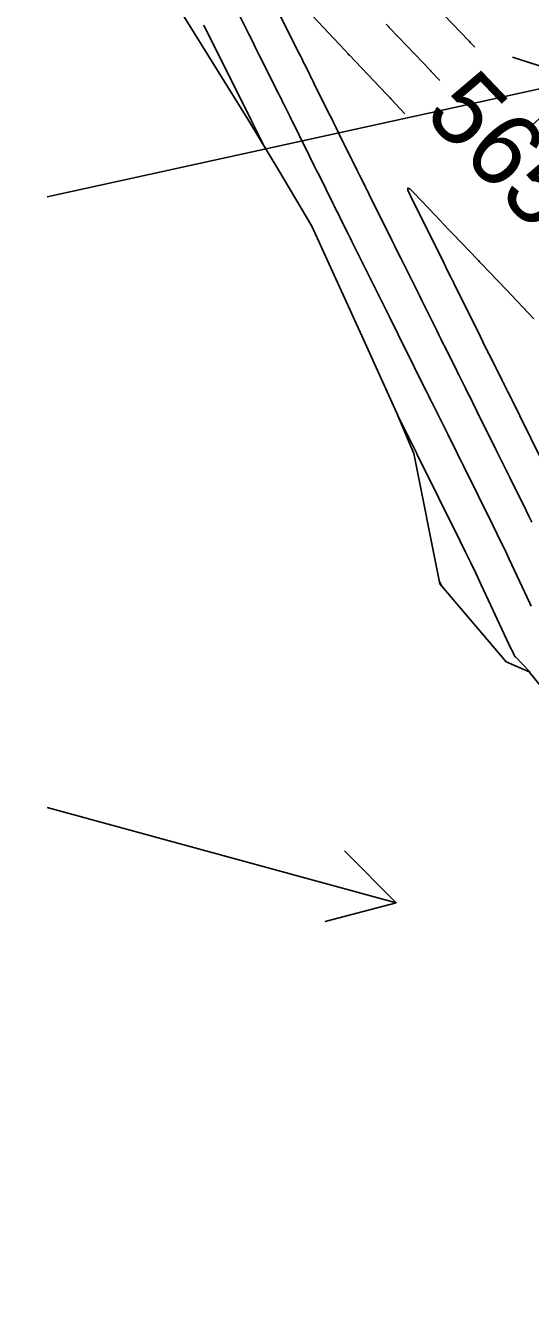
# Model space of a CAD drawing. Extents: x 954385 to 988206, y 1868364 to 1924553.
# Drawn here: x 957405.4 to 957446.7, y 1920279.3 to 1920383 of the extents above; entities that cross this region are included whole.
import ezdxf

# ---------------------------------------------------------------- set-up
doc = ezdxf.new("R2010")
doc.units = 0
for name, color, linetype in [('24', 7, 'Continuous'), ('26', 7, 'Continuous'), ('5', 7, 'Continuous'), ('6', 7, 'Continuous'), ('7', 7, 'Continuous'), ('Default', 7, 'Continuous')]:
    doc.layers.add(name, color=color, linetype=linetype)

msp = doc.modelspace()

# ---------------------------------------------------------------- linework, layer by layer
at = {"layer": '24'}
msp.add_lwpolyline([(957489.21, 1920274.25), (957480.9, 1920280.7), (957474.77, 1920288.63), (957474.48, 1920289.32), (957474.48, 1920289.32), (957470.67, 1920297.93), (957464.77, 1920306.01), (957458.75, 1920313.92), (957458.71, 1920313.98), (957454.69, 1920319.76), (957452.93, 1920322.21), (957446.59, 1920330.05), (957444.73, 1920330.87), (957439.29, 1920337.25), (957437.15, 1920347.92), (957435.77, 1920351.23), (957433.04, 1920357.26), (957428.82, 1920366.52), (957426.1, 1920371.09), (957423.66, 1920375.15), (957418.35, 1920383.68)], dxfattribs=at)
at = {"layer": '26'}
for points in [[(957407.13, 1920368.93), (957450.95, 1920378.54), (957446.52, 1920374.5), (957450.95, 1920378.54), (957445.24, 1920380.36)], [(957407.13, 1920318.93), (957435.71, 1920311.14), (957429.91, 1920309.61), (957435.71, 1920311.14), (957431.49, 1920315.4)]]:
    msp.add_lwpolyline(points, dxfattribs=at)
at = {"layer": '6'}
for points in [[(957446.77, 1920335.41), (957446.65, 1920335.68), (957444.97, 1920339.26), (957444.65, 1920339.95), (957444.32, 1920340.63), (957443.99, 1920341.31), (957443.65, 1920341.99), (957441.22, 1920346.9), (957441.08, 1920347.18), (957440.94, 1920347.47), (957440.8, 1920347.75), (957440.67, 1920348.03), (957440.11, 1920349.15), (957439.97, 1920349.44), (957439.83, 1920349.72), (957439.69, 1920350), (957439.55, 1920350.28), (957438.76, 1920351.85), (957438.71, 1920351.96), (957438.66, 1920352.06), (957438.61, 1920352.16), (957438.56, 1920352.27), (957438.35, 1920352.68), (957438.3, 1920352.78), (957438.25, 1920352.89), (957438.2, 1920352.99), (957438.14, 1920353.09), (957436.25, 1920356.9), (957436.16, 1920357.09), (957436.07, 1920357.28), (957435.97, 1920357.47), (957435.88, 1920357.66), (957435.51, 1920358.41), (957435.41, 1920358.6), (957435.32, 1920358.78), (957435.23, 1920358.97), (957435.13, 1920359.16), (957432.23, 1920365), (957432.09, 1920365.29), (957431.95, 1920365.57), (957431.8, 1920365.86), (957431.66, 1920366.14), (957431.1, 1920367.28), (957430.96, 1920367.57), (957430.81, 1920367.85), (957430.67, 1920368.14), (957430.53, 1920368.42), (957429.4, 1920370.7), (957429.2, 1920371.09), (957429.01, 1920371.48), (957428.63, 1920372.26), (957428.53, 1920372.45), (957428.43, 1920372.65), (957428.34, 1920372.84), (957428.24, 1920373.03), (957427.33, 1920374.88), (957427.23, 1920375.08), (957427.13, 1920375.29), (957427.03, 1920375.49), (957426.93, 1920375.7), (957426.52, 1920376.52), (957426.42, 1920376.72), (957426.32, 1920376.93), (957426.22, 1920377.13), (957426.12, 1920377.33), (957424.48, 1920380.59), (957424.21, 1920381.13), (957423.94, 1920381.67), (957423.67, 1920382.21), (957423.4, 1920382.74), (957422.29, 1920384.97)], [(957434.89, 1920383.08), (957435.08, 1920382.88), (957435.11, 1920382.85), (957435.14, 1920382.81), (957435.17, 1920382.78), (957435.2, 1920382.75), (957437.92, 1920379.91), (957438.08, 1920379.74), (957438.35, 1920379.45), (957438.4, 1920379.4), (957438.46, 1920379.34), (957438.51, 1920379.28), (957438.56, 1920379.23), (957439.29, 1920378.46)]]:
    msp.add_lwpolyline(points, dxfattribs=at)
at = {"layer": '7'}
for points in [[(957436.43, 1920375.74), (957435.28, 1920376.96), (957435.21, 1920377.04), (957435.13, 1920377.12), (957435.05, 1920377.2), (957434.98, 1920377.28), (957434.37, 1920377.92), (957431.88, 1920380.53), (957431.84, 1920380.56), (957431.81, 1920380.59), (957431.78, 1920380.63), (957431.75, 1920380.66), (957431.5, 1920380.93), (957425.31, 1920387.55)], [(957424.57, 1920387.05), (957427.8, 1920380.61), (957427.91, 1920380.41), (957428.01, 1920380.2), (957428.11, 1920380), (957428.21, 1920379.8), (957428.61, 1920379), (957428.71, 1920378.79), (957428.81, 1920378.59), (957428.91, 1920378.39), (957429.01, 1920378.19), (957430.24, 1920375.7), (957430.38, 1920375.42), (957430.52, 1920375.14), (957430.79, 1920374.59), (957430.86, 1920374.45), (957430.93, 1920374.31), (957431, 1920374.17), (957431.06, 1920374.03), (957432.33, 1920371.49), (957432.52, 1920371.1), (957432.72, 1920370.7), (957433.11, 1920369.92), (957433.21, 1920369.72), (957433.31, 1920369.52), (957433.41, 1920369.32), (957433.5, 1920369.13), (957435.36, 1920365.38), (957435.61, 1920364.89), (957435.85, 1920364.39), (957436.1, 1920363.9), (957436.34, 1920363.41), (957437.42, 1920361.24), (957437.62, 1920360.85), (957437.81, 1920360.45), (957438.01, 1920360.06), (957438.2, 1920359.67), (957439.03, 1920357.99), (957439.2, 1920357.65), (957439.37, 1920357.3), (957439.54, 1920356.96), (957439.72, 1920356.62), (957440.53, 1920354.97), (957440.64, 1920354.76), (957440.74, 1920354.56), (957440.84, 1920354.35), (957440.95, 1920354.14), (957441.38, 1920353.28), (957441.47, 1920353.09), (957441.57, 1920352.9), (957441.66, 1920352.71), (957441.76, 1920352.52), (957442.13, 1920351.77), (957442.23, 1920351.58), (957442.32, 1920351.39), (957442.41, 1920351.2), (957442.51, 1920351.01), (957443.93, 1920348.13), (957444.2, 1920347.59), (957444.47, 1920347.05), (957444.74, 1920346.5), (957445.01, 1920345.96), (957446.35, 1920343.25), (957446.58, 1920342.78), (957446.81, 1920342.31)], [(957424.9, 1920373.09), (957423.88, 1920375.15), (957423.84, 1920375.24), (957423.83, 1920375.26), (957423.81, 1920375.29), (957420.02, 1920382.84), (957419.95, 1920382.99)], [(957439.64, 1920383.8), (957441.63, 1920381.72), (957441.71, 1920381.64), (957441.78, 1920381.56), (957441.86, 1920381.48), (957441.93, 1920381.41), (957442.15, 1920381.18)], [(957447.67, 1920347.29), (957444.9, 1920352.89), (957444.85, 1920352.98), (957444.81, 1920353.06), (957444.77, 1920353.15), (957444.73, 1920353.23), (957444.56, 1920353.57), (957444.52, 1920353.66), (957444.47, 1920353.74), (957444.43, 1920353.83), (957444.39, 1920353.91), (957443.37, 1920355.95), (957443.3, 1920356.09), (957443.23, 1920356.23), (957443.16, 1920356.37), (957443.09, 1920356.5), (957442.82, 1920357.05), (957442.75, 1920357.19), (957442.68, 1920357.33), (957442.61, 1920357.47), (957442.55, 1920357.6), (957440.44, 1920361.85), (957440.37, 1920361.99), (957440.3, 1920362.13), (957440.24, 1920362.26), (957440.17, 1920362.4), (957439.9, 1920362.94), (957439.76, 1920363.22), (957439.63, 1920363.49), (957436.86, 1920369.06), (957436.67, 1920369.48), (957436.66, 1920369.65), (957436.82, 1920369.58), (957437.15, 1920369.27), (957438.93, 1920367.4), (957439.29, 1920367.02), (957439.65, 1920366.65), (957440.01, 1920366.27), (957440.37, 1920365.89), (957442.36, 1920363.8), (957442.45, 1920363.71), (957442.53, 1920363.62), (957442.62, 1920363.53), (957442.7, 1920363.44), (957443.39, 1920362.73), (957444.71, 1920361.34), (957446.99, 1920358.96)], [(957446.67, 1920329.96), (957446.64, 1920330.04), (957446.63, 1920330.06), (957446.62, 1920330.07), (957446.61, 1920330.08), (957446.6, 1920330.09), (957445.47, 1920331.27), (957445.43, 1920331.31), (957445.42, 1920331.32), (957445.41, 1920331.33), (957445.41, 1920331.34), (957445.4, 1920331.35), (957445.17, 1920331.85), (957445.14, 1920331.91), (957442.68, 1920337.17), (957442.25, 1920338.06), (957441.83, 1920338.96), (957441.39, 1920339.85), (957440.96, 1920340.74), (957437.44, 1920347.85), (957437.4, 1920347.92), (957437.35, 1920348.02), (957437.33, 1920348.06), (957437.32, 1920348.08), (957435.87, 1920350.98)], [(957439.24, 1920337.51), (957439.32, 1920337.34), (957439.33, 1920337.32), (957439.35, 1920337.29), (957439.36, 1920337.26), (957439.37, 1920337.23), (957439.46, 1920337.05)]]:
    msp.add_lwpolyline(points, dxfattribs=at)
at = {"layer": 'Default'}
msp.add_arc((966995.78, 1926764.93), 11459.16, 211.460692, 214.075074, dxfattribs=at)

# ---------------------------------------------------------------- texts
at = {"layer": '5'}
msp.add_text('565', height=6, rotation=313.5836, dxfattribs=at).set_placement((957437.86, 1920375.62))

doc.saveas('drawing.dxf')
